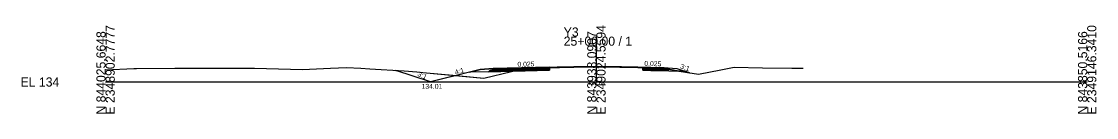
# Model space of a CAD drawing. Extents: x -26 to 2349107, y -10 to 844057.
# Drawn here: x -25.7 to 302.8, y 3990.3 to 4017.4 of the extents above; entities that cross this region are included whole.
import ezdxf

# ---------------------------------------------------------------- set-up
doc = ezdxf.new("R2010")
doc.units = 0
for name, color, linetype in [('Exist Cross Section Cell', 7, 'Continuous'), ('Exist XS Center Line Elevation Label', 7, 'Continuous'), ('Exist XS Ground Line', 7, 'Continuous'), ('Prop CMT Pvmt Course 1', 7, 'Continuous'), ('Prop CMT Pvmt Course 2', 7, 'Continuous'), ('Prop CMT Pvmt Course 3', 7, 'Continuous'), ('Prop CMT Pvmt Surface Shoulder', 7, 'Continuous'), ('Prop CMT Shld Paved Course 1', 7, 'Continuous'), ('Prop CMT Shld Paved Course 2', 7, 'Continuous'), ('Prop CMT Shld Paved Course 3', 7, 'Continuous'), ('Prop CMT Slope Grass', 7, 'Continuous'), ('Prop CMT Subgrade Earthwork', 7, 'Continuous'), ('Prop XS Ditch Standard Text', 7, 'Continuous'), ('Prop XS Earthwork Shape', 7, 'Continuous'), ('Prop XS SE Text', 7, 'Continuous'), ('Prop XS Side Slope Text', 7, 'Continuous')]:
    doc.layers.add(name, color=color, linetype=linetype)

msp = doc.modelspace()

# ---------------------------------------------------------------- linework, layer by layer
at = {"layer": 'Exist Cross Section Cell'}
for p, q in [((150, 4000), (150, 4013.95)), ((0, 4000), (150, 4000)), ((150, 4000), (300, 4000))]:
    msp.add_line(p, q, dxfattribs=at)
at = {"layer": 'Exist XS Ground Line'}
msp.add_lwpolyline([(0, 4003.7), (8.68, 4004.16), (9.12, 4004.19), (9.45, 4004.19), (21.19, 4004.22), (26.58, 4004.25), (33.51, 4004.25), (43.71, 4004.25), (44.94, 4004.26), (45.51, 4004.23), (60.23, 4003.89), (68.75, 4004.28), (73.6, 4004.5), (77.97, 4004.23), (80.77, 4004.08), (91.26, 4003.39), (95.14, 4003.11), (96.95, 4002.97), (115.59, 4001.2), (124.09, 4003.26), (126, 4003.7), (126.74, 4003.79), (131.11, 4004.27), (131.74, 4004.3), (132.74, 4004.34), (135.25, 4004.41), (135.63, 4004.42), (135.96, 4004.43), (136.97, 4004.46), (137.99, 4004.48), (138.72, 4004.5), (139.79, 4004.52), (141.27, 4004.57), (141.79, 4004.59), (143.1, 4004.6), (145.16, 4004.63), (145.57, 4004.63), (147.5, 4004.63), (148.19, 4004.64), (150, 4004.65), (151.01, 4004.65), (154.1, 4004.64), (155.89, 4004.62), (157.17, 4004.6), (157.68, 4004.6), (158.4, 4004.58), (159.48, 4004.56), (160.26, 4004.55), (162.64, 4004.5), (163.44, 4004.48), (164.19, 4004.45), (166.61, 4004.4), (167.66, 4004.35), (168.11, 4004.33), (169.4, 4004.17), (171.33, 4004.02), (176.58, 4003.1), (181.16, 4002.44), (188.04, 4003.76), (192.13, 4004.53), (200.75, 4004.4), (209.78, 4004.23), (210.99, 4004.26), (213.18, 4004.3)], dxfattribs=at)
at = {"layer": 'Prop CMT Pvmt Course 1'}
for p, q in [((122.5, 4004.22), (122.5, 4003.97)), ((135.63, 4004.54), (135.63, 4004.29)), ((164.19, 4004.58), (164.19, 4004.33)), ((166.63, 4004.52), (166.63, 4004.27))]:
    msp.add_line(p, q, dxfattribs=at)
at = {"layer": 'Prop CMT Pvmt Course 2'}
for p, q in [((122.5, 4003.97), (122.5, 4003.63)), ((135.63, 4004.29), (135.63, 4003.96)), ((164.19, 4004.33), (164.19, 4003.99)), ((166.63, 4004.27), (166.63, 4003.93))]:
    msp.add_line(p, q, dxfattribs=at)
at = {"layer": 'Prop CMT Pvmt Course 3'}
for p, q in [((122.5, 4003.63), (122.5, 4003.26)), ((135.63, 4003.96), (135.63, 4003.59)), ((164.19, 4003.99), (164.19, 4003.62)), ((166.63, 4003.93), (166.63, 4003.56))]:
    msp.add_line(p, q, dxfattribs=at)
at = {"layer": 'Prop CMT Pvmt Surface Shoulder'}
for p, q in [((135.63, 4004.54), (118.5, 4004.12)), ((164.19, 4004.58), (166.63, 4004.52)), ((166.63, 4004.52), (170.63, 4004.42))]:
    msp.add_line(p, q, dxfattribs=at)
msp.add_lwpolyline([(135.63, 4004.54), (135.96, 4004.56), (136.97, 4004.58), (137.99, 4004.61), (138.72, 4004.62), (139.79, 4004.65), (141.27, 4004.7), (141.79, 4004.71), (143.1, 4004.73), (145.16, 4004.76), (145.56, 4004.76), (147.49, 4004.75), (148.19, 4004.77), (150, 4004.77), (151.01, 4004.78), (154.1, 4004.76), (155.89, 4004.74), (157.17, 4004.73), (157.69, 4004.72), (158.4, 4004.71), (159.48, 4004.69), (160.26, 4004.67), (162.65, 4004.62), (163.45, 4004.6), (164.19, 4004.58)], dxfattribs=at)
at = {"layer": 'Prop CMT Shld Paved Course 1'}
for p, q in [((118.24, 4003.86), (135.63, 4004.29)), ((118.5, 4004.12), (118.24, 4003.86)), ((135.63, 4004.54), (118.5, 4004.12)), ((122.5, 4003.97), (122.5, 4004.22)), ((135.63, 4004.29), (135.63, 4004.54)), ((164.19, 4004.58), (166.63, 4004.52)), ((164.19, 4004.33), (164.19, 4004.58)), ((166.63, 4004.27), (164.19, 4004.33)), ((166.63, 4004.27), (166.63, 4004.52)), ((166.63, 4004.52), (170.63, 4004.42)), ((170.89, 4004.16), (166.63, 4004.27)), ((170.63, 4004.42), (170.89, 4004.16))]:
    msp.add_line(p, q, dxfattribs=at)
at = {"layer": 'Prop CMT Shld Paved Course 2'}
for p, q in [((117.9, 4003.52), (135.63, 4003.96)), ((118.24, 4003.86), (117.9, 4003.52)), ((135.63, 4004.29), (118.24, 4003.86)), ((122.5, 4003.63), (122.5, 4003.97)), ((135.63, 4003.96), (135.63, 4004.29)), ((164.19, 4004.33), (166.63, 4004.27)), ((164.19, 4003.99), (164.19, 4004.33)), ((166.63, 4003.93), (164.19, 4003.99)), ((166.63, 4003.93), (166.63, 4004.27)), ((166.63, 4004.27), (170.89, 4004.16)), ((171.15, 4003.82), (166.63, 4003.93)), ((170.89, 4004.16), (171.23, 4003.82))]:
    msp.add_line(p, q, dxfattribs=at)
at = {"layer": 'Prop CMT Shld Paved Course 3'}
for p, q in [((117.02, 4003.12), (135.63, 4003.59)), ((117.4, 4003.51), (117.02, 4003.12)), ((117.9, 4003.52), (117.4, 4003.51)), ((135.63, 4003.96), (117.9, 4003.52)), ((122.5, 4003.26), (122.5, 4003.63)), ((135.63, 4003.59), (135.63, 4003.96)), ((164.19, 4003.99), (166.63, 4003.93)), ((164.19, 4003.62), (164.19, 4003.99)), ((166.63, 4003.56), (164.19, 4003.62)), ((166.63, 4003.56), (166.63, 4003.93)), ((166.63, 4003.93), (171.23, 4003.82)), ((172.03, 4003.42), (166.63, 4003.56)), ((171.23, 4003.82), (171.73, 4003.81)), ((171.73, 4003.81), (172.12, 4003.42))]:
    msp.add_line(p, q, dxfattribs=at)
at = {"layer": 'Prop CMT Slope Grass'}
for p, q in [((99.34, 4000.01), (88.68, 4003.56)), ((114.5, 4003.8), (99.34, 4000.01)), ((118.5, 4004.12), (114.5, 4003.8)), ((170.63, 4004.42), (174.63, 4004.1)), ((174.63, 4004.1), (178.42, 4002.83))]:
    msp.add_line(p, q, dxfattribs=at)
at = {"layer": 'Prop CMT Subgrade Earthwork'}
for p, q in [((117.02, 4003.12), (111.22, 4002.98)), ((135.63, 4003.59), (117.02, 4003.12)), ((135.63, 4003.59), (135.63, 4004.42)), ((164.19, 4003.62), (164.19, 4004.45)), ((164.19, 4003.62), (166.63, 4003.56)), ((166.63, 4003.56), (172.12, 4003.42)), ((172.12, 4003.42), (177.03, 4003.3))]:
    msp.add_line(p, q, dxfattribs=at)
at = {"layer": 'Prop XS Earthwork Shape'}
for points in [[(107.27, 4001.99), (99.34, 4000.01), (88.68, 4003.56), (91.26, 4003.39), (95.14, 4003.11), (96.95, 4002.97)], [(107.27, 4001.99), (115.59, 4001.2), (124.09, 4003.26), (124.28, 4003.3), (117.02, 4003.12), (111.22, 4002.98)], [(135.96, 4004.56), (136.97, 4004.58), (137.99, 4004.61), (138.72, 4004.62), (139.79, 4004.65), (141.27, 4004.7), (141.79, 4004.71), (143.1, 4004.73), (145.16, 4004.76), (145.56, 4004.76), (147.49, 4004.75), (148.19, 4004.77), (150, 4004.77), (151.01, 4004.78), (154.1, 4004.76), (155.89, 4004.74), (157.17, 4004.73), (157.69, 4004.72), (158.4, 4004.71), (159.48, 4004.69), (160.26, 4004.67), (162.65, 4004.62), (163.45, 4004.6), (164.19, 4004.58), (166.63, 4004.52), (170.63, 4004.42), (174.63, 4004.1), (177.03, 4003.3), (175.17, 4003.34), (171.33, 4004.02), (169.4, 4004.17), (168.11, 4004.33), (167.66, 4004.35), (166.61, 4004.4), (164.19, 4004.45), (163.44, 4004.48), (162.64, 4004.5), (160.26, 4004.55), (159.48, 4004.56), (158.4, 4004.58), (157.68, 4004.6), (157.17, 4004.6), (155.89, 4004.62), (154.1, 4004.64), (151.01, 4004.65), (150, 4004.65), (148.19, 4004.64), (147.5, 4004.63), (145.57, 4004.63), (145.16, 4004.63), (143.1, 4004.6), (141.79, 4004.59), (141.27, 4004.57), (139.79, 4004.52), (138.72, 4004.5), (137.99, 4004.48), (136.97, 4004.46), (135.96, 4004.43), (135.63, 4004.42), (135.25, 4004.41), (132.74, 4004.34), (131.74, 4004.3), (131.11, 4004.27), (126.74, 4003.79), (126, 4003.7), (124.28, 4003.3), (117.02, 4003.12), (111.22, 4002.98), (114.5, 4003.8), (118.5, 4004.12), (135.63, 4004.54)], [(124.28, 4003.3), (126, 4003.7), (126.74, 4003.79), (131.11, 4004.27), (131.74, 4004.3), (132.74, 4004.34), (135.25, 4004.41), (135.63, 4004.42), (135.63, 4003.59)], [(172.12, 4003.42), (175.17, 4003.34), (171.33, 4004.02), (169.4, 4004.17), (168.11, 4004.33), (167.66, 4004.35), (166.61, 4004.4), (164.19, 4004.45), (164.19, 4003.62), (166.63, 4003.56)], [(175.17, 4003.34), (176.58, 4003.1), (178.42, 4002.83), (177.03, 4003.3)]]:
    msp.add_lwpolyline(points, close=True, dxfattribs=at)

# ---------------------------------------------------------------- texts
at = {"layer": 'Exist Cross Section Cell'}
for s, p in [('N 844025.6648', (0, 3990)), ('E 2348902.7777', (2.8, 3990)), ('N 843938.0907', (150, 3990)), ('E 2349024.5594', (152.8, 3990)), ('N 843850.5166', (300, 3990)), ('E 2349146.3410', (302.8, 3990))]:
    msp.add_text(s, height=2.8, rotation=90, dxfattribs=at).set_placement(p)
for s, p in [('Y3', (140, 4013.95)), ('25+00.00 / 1', (140, 4011.15)), ('EL 134', (-26, 3998.6))]:
    msp.add_text(s, height=2.8, dxfattribs=at).set_placement(p)
at = {"layer": 'Exist XS Center Line Elevation Label'}
msp.add_text('138.65', height=1.2, dxfattribs=at).set_placement((147.52, 3999.05))
at = {"layer": 'Prop XS Ditch Standard Text'}
msp.add_text('134.01', height=1.5, dxfattribs=at).set_placement((96.57, 3997.92))
at = {"layer": 'Prop XS SE Text'}
for rotation, p in [(1.4321, (125.9, 4004.68)), (358.2177, (164.64, 4004.97))]:
    msp.add_text('0.025', height=1.5, rotation=rotation, dxfattribs=at).set_placement(p)
at = {"layer": 'Prop XS Side Slope Text'}
for s, rotation, p in [('3:1', 340.7803, (175.49, 4004.21)), ('3:1', 334.1575, (95.19, 4001.96)), ('4:1', 16.0126, (106.95, 4002.23))]:
    msp.add_text(s, height=1.5, rotation=rotation, dxfattribs=at).set_placement(p)

doc.saveas('drawing.dxf')
